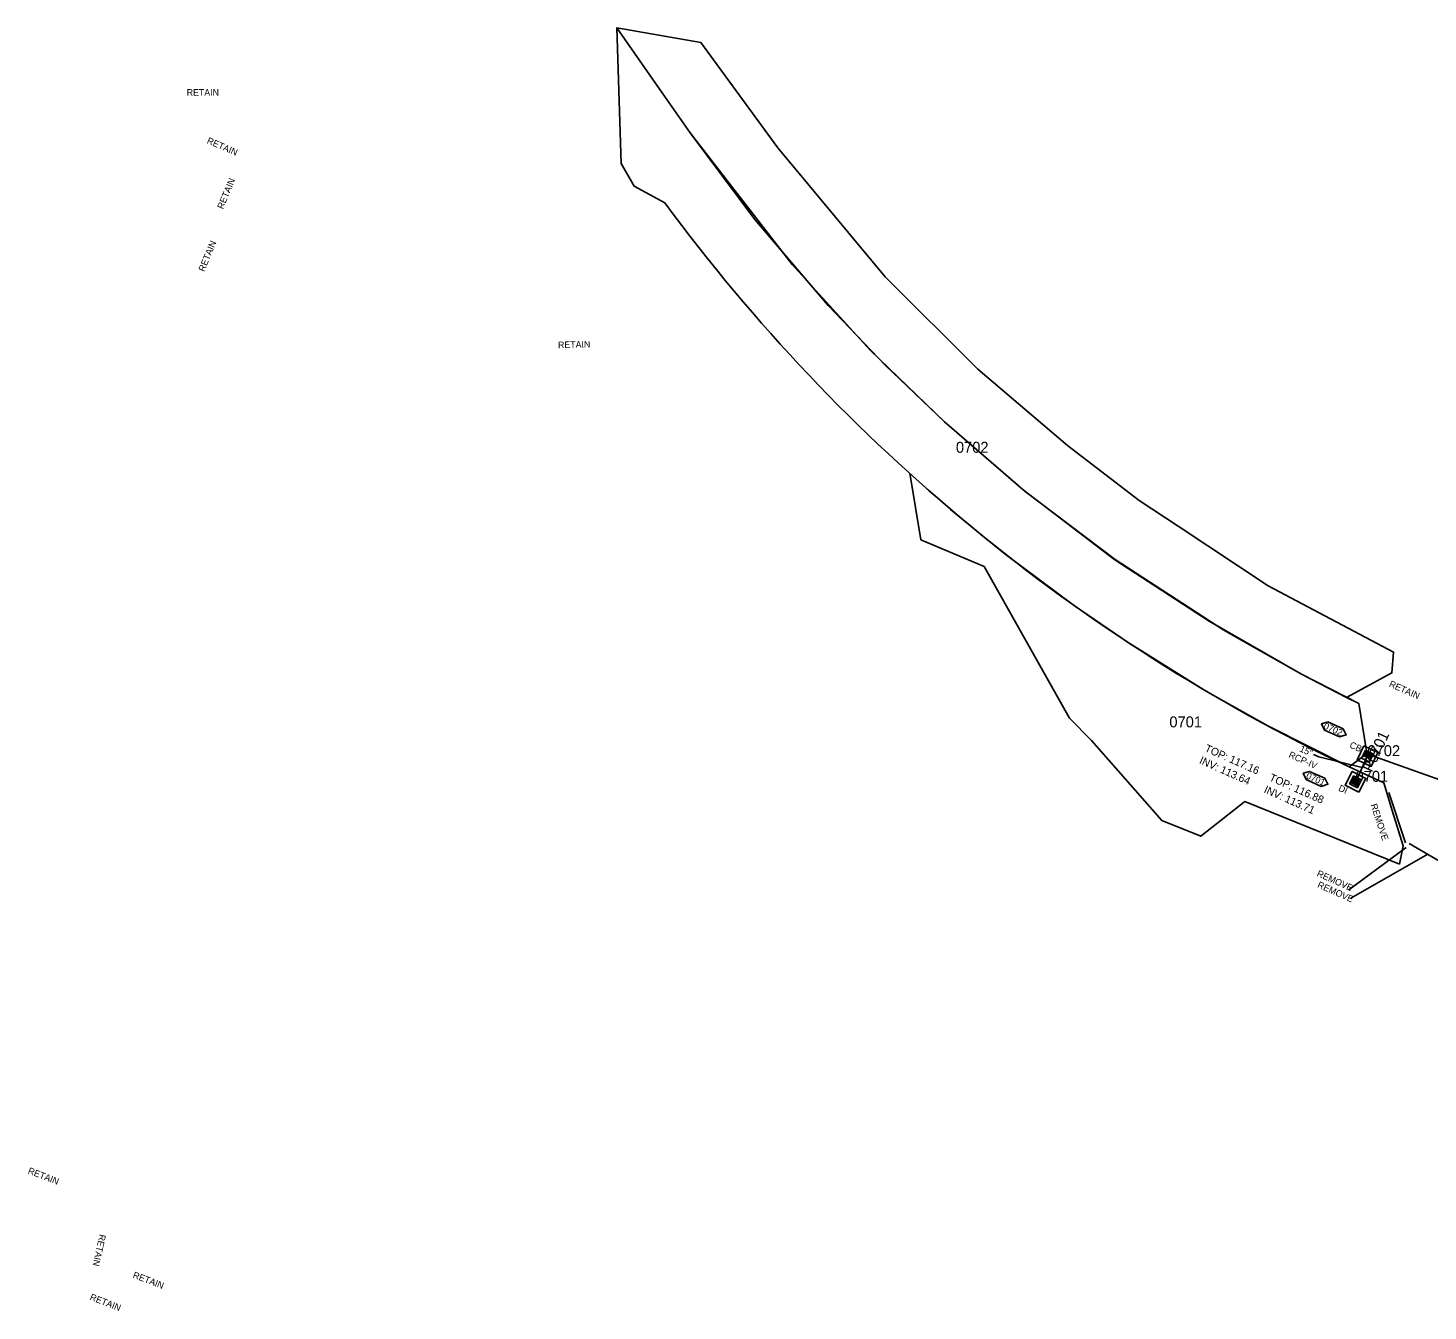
# Model space of a CAD drawing. Extents: x 2296558 to 2299313, y 599200 to 601383.
# Drawn here: x 2297992 to 2298630, y 599379 to 599964 of the extents above; entities that cross this region are included whole.
import ezdxf

# ---------------------------------------------------------------- set-up
doc = ezdxf.new("R2010")
doc.units = 0
for name, color, linetype in [('Old_Level_2', 7, 'Continuous'), ('Prop Drainage Structure Box Number Symbol CELL', 7, 'Continuous'), ('Prop Drainage Structure Catch Basin Grate 840 03F CELL', 7, 'Continuous'), ('Prop Drainage Structure Catch Basin Grate 840 03F Label', 7, 'Continuous'), ('Prop Drainage Structure Drop Inlet Grate 840 16 CELL', 7, 'Continuous'), ('Prop Drainage Structure Drop Inlet Grate 840 16 Label', 7, 'Continuous'), ('Prop Drainage Structure Pipe RCP 15in Class IV', 7, 'Continuous'), ('Prop Drainage Structure Pipe RCP 15in Class IV Label', 7, 'Continuous'), ('Prop Drainage Structure Pipe Removal', 7, 'Continuous'), ('Prop Drainage Structure Plot Symbol 20 Scale', 7, 'Continuous'), ('Prop Drainage Structure Plot Symbol 50 Scale', 7, 'Continuous'), ('Prop Drainage Structure Removal Label', 7, 'Continuous'), ('Prop Drainage Structure Retain Label', 7, 'Continuous'), ('Prop Drainage Structure Tops and Inverts LABEL', 7, 'Continuous'), ('Prop Plan Preparation Watershed Post Construction', 7, 'Continuous'), ('Scratch_Level_1', 7, 'Continuous'), ('Scratch_Level_3', 7, 'Continuous'), ('Scratch_Level_5', 7, 'Continuous')]:
    doc.layers.add(name, color=color, linetype=linetype)

msp = doc.modelspace()

# ---------------------------------------------------------------- linework, layer by layer
at = {"layer": 'Old_Level_2'}
msp.add_lwpolyline([(2298260.2, 599964.1), (2298279.87, 599936.01), (2298293.63, 599916.36), (2298323.17, 599876.83), (2298356.65, 599837.47), (2298382.68, 599810.13), (2298409.57, 599784.41), (2298445.59, 599753.44), (2298487.26, 599721.52), (2298530.32, 599693.51), (2298572.52, 599669.34), (2298592.97, 599658.81), (2298613.69, 599670.01), (2298614.45, 599679.48), (2298557.31, 599709.73), (2298516.17, 599736.87), (2298498.41, 599748.54), (2298465.72, 599773.7), (2298424.87, 599808.45), (2298382.55, 599850.67), (2298333.58, 599909.44), (2298298.59, 599957.52)], close=True, dxfattribs=at)
at = {"layer": 'Prop Drainage Structure Box Number Symbol CELL'}
for points in [[(2298584.48, 599647.61), (2298591.38, 599644.53), (2298592.84, 599641.75), (2298589.8, 599640.76), (2298582.9, 599643.84), (2298581.58, 599646.78), (2298584.48, 599647.61)], [(2298576.12, 599625.08), (2298583.02, 599622), (2298584.48, 599619.23), (2298581.44, 599618.23), (2298574.54, 599621.31), (2298573.22, 599624.25), (2298576.12, 599625.08)]]:
    msp.add_lwpolyline(points, dxfattribs=at)
at = {"layer": 'Prop Drainage Structure Catch Basin Grate 840 03F CELL'}
for p, q in [((2298601.41, 599632.66), (2298601.39, 599632.72)), ((2298601.67, 599632.54), (2298601.5, 599632.97)), ((2298601.5, 599632.77), (2298601.53, 599632.7)), ((2298601.59, 599633.51), (2298601.59, 599633.51)), ((2298601.93, 599632.42), (2298601.62, 599633.22)), ((2298601.62, 599633.02), (2298601.79, 599632.58)), ((2298602.18, 599632.3), (2298601.74, 599633.47)), ((2298601.74, 599633.27), (2298602.04, 599632.46)), ((2298602.44, 599632.18), (2298601.85, 599633.72)), ((2298601.85, 599633.52), (2298602.3, 599632.34)), ((2298601.97, 599633.77), (2298602.56, 599632.22)), ((2298602.09, 599634.02), (2298602.68, 599632.46)), ((2298602.26, 599634.13), (2298602.8, 599632.71)), ((2298602.84, 599632.8), (2298602.4, 599633.97)), ((2298602.74, 599632.29), (2298602.81, 599632.1)), ((2298602.86, 599632.54), (2298603.07, 599631.98)), ((2298603.07, 599633.3), (2298602.91, 599633.73)), ((2298602.96, 599632.91), (2298602.96, 599632.91)), ((2298602.97, 599632.79), (2298603.33, 599631.86)), ((2298603.09, 599633.05), (2298603.58, 599631.74)), ((2298603.21, 599633.3), (2298603.84, 599631.62)), ((2298603.84, 599631.83), (2298603.25, 599633.39)), ((2298603.37, 599633.78), (2298603.37, 599633.78)), ((2298603.96, 599632.08), (2298603.42, 599633.49)), ((2298603.54, 599633.53), (2298604.08, 599632.12)), ((2298604.08, 599632.33), (2298603.68, 599633.37)), ((2298603.8, 599633.41), (2298604.19, 599632.37)), ((2298604.19, 599632.58), (2298603.94, 599633.25)), ((2298604.06, 599633.29), (2298604.31, 599632.62)), ((2298604.31, 599632.83), (2298604.2, 599633.13)), ((2298604.31, 599633.17), (2298604.43, 599632.87)), ((2298604.31, 599632.25), (2298604.31, 599632.25)), ((2298602.31, 599631.52), (2298602.31, 599631.52))]:
    msp.add_line(p, q, dxfattribs=at)
for points in [[(2298603.88, 599631.34), (2298601.16, 599632.6), (2298602.01, 599634.42), (2298604.72, 599633.15), (2298603.67, 599630.88), (2298600.95, 599632.15), (2298601.16, 599632.6)], [(2298601.17, 599632.61), (2298602.01, 599634.4), (2298604.71, 599633.14), (2298603.87, 599631.35), (2298601.17, 599632.61)], [(2298603.75, 599631.55), (2298601.34, 599632.67), (2298602.07, 599634.24), (2298604.54, 599633.08), (2298603.84, 599631.57)], [(2298602.68, 599632.46), (2298602.6, 599632.3), (2298601.97, 599633.97)], [(2298602.8, 599632.71), (2298602.72, 599632.55), (2298602.14, 599634.09)], [(2298602.51, 599634.01), (2298602.91, 599632.96), (2298602.84, 599632.8)], [(2298602.77, 599633.89), (2298603.03, 599633.21), (2298602.96, 599633.05), (2298602.65, 599633.85)], [(2298602.7, 599632.06), (2298602.67, 599632.14), (2298602.74, 599632.29)], [(2298602.95, 599631.94), (2298602.78, 599632.39), (2298602.86, 599632.54)], [(2298603.21, 599631.82), (2298602.9, 599632.64), (2298602.97, 599632.79)], [(2298603.15, 599633.46), (2298603.07, 599633.3), (2298602.91, 599633.73)], [(2298603.47, 599631.7), (2298603.02, 599632.89), (2298603.09, 599633.05)], [(2298603.03, 599633.77), (2298603.15, 599633.46), (2298603.07, 599633.3)], [(2298603.73, 599631.58), (2298603.13, 599633.14), (2298603.21, 599633.3)], [(2298603.25, 599633.39), (2298603.32, 599633.55), (2298603.96, 599631.87)]]:
    msp.add_lwpolyline(points, dxfattribs=at)
for centre, start, end in [((2298601.45, 599632.74), 20.73937, 200.73937), ((2298601.47, 599632.68), 200.73937, 20.73937), ((2298601.56, 599632.99), 20.73937, 200.73937), ((2298601.68, 599633.24), 20.73937, 200.73937), ((2298601.73, 599632.56), 200.73937, 20.73937), ((2298601.8, 599633.5), 20.73937, 200.73937), ((2298601.91, 599633.75), 20.73937, 200.73937), ((2298601.98, 599632.44), 200.73937, 20.73937), ((2298602.03, 599634), 20.73937, 200.73937), ((2298602.2, 599634.11), 20.73937, 200.73937), ((2298602.24, 599632.32), 200.73937, 20.73937), ((2298602.46, 599633.99), 20.73937, 200.73937), ((2298602.5, 599632.2), 200.73937, 20.73937), ((2298602.71, 599633.87), 20.73937, 200.73937), ((2298602.75, 599632.08), 200.73937, 20.73937), ((2298602.97, 599633.75), 20.73937, 200.73937), ((2298603.01, 599631.96), 200.73937, 20.73937), ((2298603.27, 599631.84), 200.73937, 20.73937), ((2298603.48, 599633.51), 20.73937, 200.73937), ((2298603.74, 599633.39), 20.73937, 200.73937), ((2298603.9, 599631.85), 200.73937, 20.73937), ((2298604, 599633.27), 20.73937, 200.73937), ((2298604.02, 599632.1), 200.73937, 20.73937), ((2298604.13, 599632.35), 200.7386, 20.7386), ((2298604.25, 599633.15), 20.73937, 200.73937), ((2298604.25, 599632.6), 200.7386, 20.7386), ((2298604.37, 599632.85), 200.73937, 20.73937), ((2298603.53, 599631.72), 200.73937, 20.73937), ((2298603.78, 599631.6), 200.73937, 20.73937)]:
    msp.add_arc(centre, 0.0625, start, end, dxfattribs=at)
at = {"layer": 'Prop Drainage Structure Drop Inlet Grate 840 16 CELL'}
for p, q in [((2298595.53, 599621.11), (2298595.53, 599621.11)), ((2298596.52, 599619.2), (2298596.52, 599619.2)), ((2298597.09, 599620.31), (2298597.09, 599620.31)), ((2298597.66, 599621.43), (2298597.66, 599621.43)), ((2298598.65, 599619.52), (2298598.65, 599619.52))]:
    msp.add_line(p, q, dxfattribs=at)
for points in [[(2298598.08, 599618.41), (2298594.96, 599620), (2298596.1, 599622.22), (2298599.22, 599620.63), (2298599.22, 599620.63), (2298598.08, 599618.41)], [(2298598.04, 599618.52), (2298595.07, 599620.03), (2298596.13, 599622.11), (2298599.1, 599620.6), (2298599.1, 599620.6), (2298598.04, 599618.52)], [(2298597.61, 599621.35), (2298596.56, 599619.28), (2298595.09, 599620.04), (2298596.14, 599622.1), (2298599.09, 599620.59), (2298598.04, 599618.53), (2298596.56, 599619.28)], [(2298596.51, 599619.45), (2298595.26, 599620.08), (2298595.34, 599620.23), (2298596.58, 599619.6), (2298596.51, 599619.45)], [(2298596.63, 599619.69), (2298595.38, 599620.32), (2298595.46, 599620.47), (2298596.7, 599619.84), (2298596.63, 599619.69)], [(2298596.75, 599619.92), (2298595.51, 599620.56), (2298595.58, 599620.71), (2298596.82, 599620.07), (2298596.75, 599619.92)], [(2298596.87, 599620.16), (2298595.63, 599620.79), (2298595.7, 599620.94), (2298596.95, 599620.31), (2298596.87, 599620.16)], [(2298596.99, 599620.4), (2298595.75, 599621.03), (2298595.82, 599621.18), (2298597.07, 599620.55), (2298596.99, 599620.4)], [(2298597.11, 599620.63), (2298595.87, 599621.27), (2298595.94, 599621.42), (2298597.19, 599620.78), (2298597.11, 599620.63)], [(2298597.23, 599620.87), (2298595.99, 599621.5), (2298596.06, 599621.65), (2298597.31, 599621.02), (2298597.23, 599620.87)], [(2298597.35, 599621.11), (2298596.11, 599621.74), (2298596.2, 599621.93), (2298597.45, 599621.29), (2298597.35, 599621.11), (2298597.35, 599621.11)], [(2298597.97, 599618.7), (2298596.73, 599619.34), (2298596.81, 599619.49), (2298598.05, 599618.85), (2298597.97, 599618.7)], [(2298598.1, 599618.94), (2298596.85, 599619.57), (2298596.93, 599619.72), (2298598.17, 599619.09), (2298598.1, 599618.94)], [(2298598.22, 599619.18), (2298596.97, 599619.81), (2298597.05, 599619.96), (2298598.29, 599619.33), (2298598.22, 599619.18)], [(2298598.34, 599619.41), (2298597.09, 599620.05), (2298597.17, 599620.2), (2298598.41, 599619.56), (2298598.34, 599619.41)], [(2298598.46, 599619.65), (2298597.21, 599620.28), (2298597.29, 599620.43), (2298598.53, 599619.8), (2298598.46, 599619.65)], [(2298598.58, 599619.89), (2298597.33, 599620.52), (2298597.41, 599620.67), (2298598.65, 599620.04), (2298598.58, 599619.89)], [(2298598.7, 599620.12), (2298597.45, 599620.76), (2298597.53, 599620.91), (2298598.77, 599620.27), (2298598.7, 599620.12)], [(2298598.82, 599620.36), (2298597.57, 599620.99), (2298597.67, 599621.18), (2298598.91, 599620.55), (2298598.82, 599620.36), (2298598.82, 599620.36)]]:
    msp.add_lwpolyline(points, dxfattribs=at)
at = {"layer": 'Prop Drainage Structure Pipe RCP 15in Class IV'}
for p, q in [((2298604.31, 599632.25), (2298836.12, 599549.71)), ((2298597.66, 599621.43), (2298602.31, 599631.52))]:
    msp.add_line(p, q, dxfattribs=at)
at = {"layer": 'Prop Drainage Structure Pipe RCP 15in Class IV Label'}
msp.add_lwpolyline([(2298600.18, 599626.89), (2298580.33, 599631.73), (2298577.9, 599632.82)], dxfattribs=at)
at = {"layer": 'Prop Drainage Structure Pipe Removal'}
for p, q in [((2298612.27, 599615.41), (2298619.86, 599592.49)), ((2298621.47, 599592.18), (2298642.74, 599579.93))]:
    msp.add_line(p, q, dxfattribs=at)
at = {"layer": 'Prop Drainage Structure Plot Symbol 20 Scale'}
for points in [[(2298601.57, 599634.67), (2298605.2, 599632.98), (2298603.51, 599629.35), (2298599.88, 599631.04)], [(2298597.96, 599617.63), (2298594.4, 599619.44), (2298596.21, 599623), (2298599.78, 599621.19)]]:
    msp.add_lwpolyline(points, close=True, dxfattribs=at)
at = {"layer": 'Prop Drainage Structure Plot Symbol 50 Scale'}
for points in [[(2298600.84, 599636.66), (2298607.19, 599633.7), (2298604.23, 599627.36), (2298597.89, 599630.31)], [(2298598.62, 599615.61), (2298592.38, 599618.78), (2298595.56, 599625.02), (2298601.8, 599621.85)]]:
    msp.add_lwpolyline(points, close=True, dxfattribs=at)
at = {"layer": 'Prop Drainage Structure Removal Label'}
for p, q in [((2298593.99, 599571.09), (2298620.23, 599590.3)), ((2298594.98, 599567.24), (2298630.05, 599587.24))]:
    msp.add_line(p, q, dxfattribs=at)
at = {"layer": 'Prop Plan Preparation Watershed Post Construction'}
for p, q in [((2298572.52, 599669.34), (2298598.64, 599656.02)), ((2298594.18, 599627.1), (2298600.94, 599632.12)), ((2298617.11, 599582.81), (2298546.66, 599611.39))]:
    msp.add_line(p, q, dxfattribs=at)
for points in [[(2298598.64, 599656.02), (2298592.97, 599658.81), (2298589.76, 599660.46), (2298572.52, 599669.34), (2298536.98, 599689.47), (2298487.45, 599721.77), (2298446.47, 599752.73), (2298409.57, 599784.41), (2298375.74, 599817.17), (2298340.12, 599856.26), (2298293.63, 599916.36), (2298279.87, 599936.01), (2298260.2, 599964.1), (2298262.2, 599902.24), (2298268.19, 599892.01), (2298282.15, 599884.35)], [(2298394.01, 599760.17), (2298393.84, 599760.88), (2298402.32, 599753.32), (2298415.41, 599742.05), (2298424.45, 599734.55), (2298437.37, 599724.19), (2298468.94, 599700.57), (2298493.34, 599683.86), (2298527.42, 599662.57), (2298532.93, 599659.34), (2298557.09, 599645.84), (2298594.18, 599627.1), (2298610, 599619.78), (2298613.84, 599607.28), (2298618.83, 599591.09), (2298617.11, 599582.81)], [(2298466.59, 599649.41), (2298427.71, 599718.53), (2298398.87, 599730.74), (2298394.01, 599760.17)], [(2298600.95, 599632.15), (2298602.02, 599634.41), (2298598.64, 599656.02), (2298592.97, 599658.81), (2298572.52, 599669.34)], [(2298546.66, 599611.39), (2298526.49, 599595.47), (2298508.74, 599602.66), (2298476.72, 599639.14), (2298466.59, 599649.41)]]:
    msp.add_lwpolyline(points, dxfattribs=at)
msp.add_arc((2298948.93, 600375.25), 828, 216.36176, 244.63161, dxfattribs=at)

# ---------------------------------------------------------------- texts
at = {"layer": 'Prop Drainage Structure Box Number Symbol CELL'}
for s, rotation, p in [('0702', 335.943, (2298582.22, 599644.74)), ('0701', 335.94306, (2298574.26, 599622.04))]:
    msp.add_text(s, height=3, rotation=rotation, dxfattribs=at).set_placement(p)
at = {"layer": 'Prop Drainage Structure Catch Basin Grate 840 03F Label'}
msp.add_text('CB', height=3, rotation=335.94306, dxfattribs=at).set_placement((2298594.07, 599636.03))
at = {"layer": 'Prop Drainage Structure Drop Inlet Grate 840 16 Label'}
msp.add_text('DI', height=3, rotation=335.94306, dxfattribs=at).set_placement((2298588.99, 599616.35))
at = {"layer": 'Prop Drainage Structure Pipe RCP 15in Class IV Label'}
for s, p in [('RCP-IV ', (2298566.32, 599631.58)), ('15" ', (2298571.28, 599634.29))]:
    msp.add_text(s, height=3, rotation=335.94306, dxfattribs=at).set_placement(p)
at = {"layer": 'Prop Drainage Structure Removal Label'}
for rotation, p in [(288.31139, (2298603.9, 599609.76)), (335.94306, (2298579.16, 599577.42)), (335.94476, (2298579.43, 599572.29))]:
    msp.add_text('REMOVE', height=3, rotation=rotation, dxfattribs=at).set_placement(p)
at = {"layer": 'Prop Drainage Structure Retain Label'}
msp.add_text('RETAIN', height=3, dxfattribs=at).set_placement((2298064.07, 599933.22))
for rotation, p in [(336.40889, (2298073.01, 599911.64)), (67.58361, (2298080.64, 599881.25)), (67.58361, (2298072.08, 599852.74)), (1.49278, (2298233.44, 599818.03)), (336.08556, (2298612.09, 599663.87)), (338.76333, (2297991.4, 599441.79)), (257.33199, (2298024.36, 599414.14)), (339.27861, (2298039.24, 599394.2)), (338.76333, (2298019.65, 599384.18))]:
    msp.add_text('RETAIN', height=3, rotation=rotation, dxfattribs=at).set_placement(p)
at = {"layer": 'Prop Drainage Structure Tops and Inverts LABEL'}
for s, p in [('INV: 113.64', (2298525.55, 599628.87)), ('TOP: 117.16', (2298528, 599634.35)), ('TOP: 116.88', (2298557.44, 599621.04)), ('INV: 113.71', (2298555, 599615.56))]:
    msp.add_text(s, height=3.5, rotation=335.94306, dxfattribs=at).set_placement(p)
at = {"layer": 'Scratch_Level_1'}
for s, p in [('0702', (2298414.85, 599770.38)), ('0701', (2298512.19, 599645.14))]:
    msp.add_text(s, height=5, dxfattribs=at).set_placement(p)
at = {"layer": 'Scratch_Level_3'}
msp.add_text('P0701', height=5, rotation=65.23704, dxfattribs=at).set_placement((2298604.52, 599624.38))
at = {"layer": 'Scratch_Level_5'}
for s, p in [('0702', (2298602.54, 599632.01)), ('0701', (2298597.09, 599620.31))]:
    msp.add_text(s, height=5, dxfattribs=at).set_placement(p)

doc.saveas('drawing.dxf')
